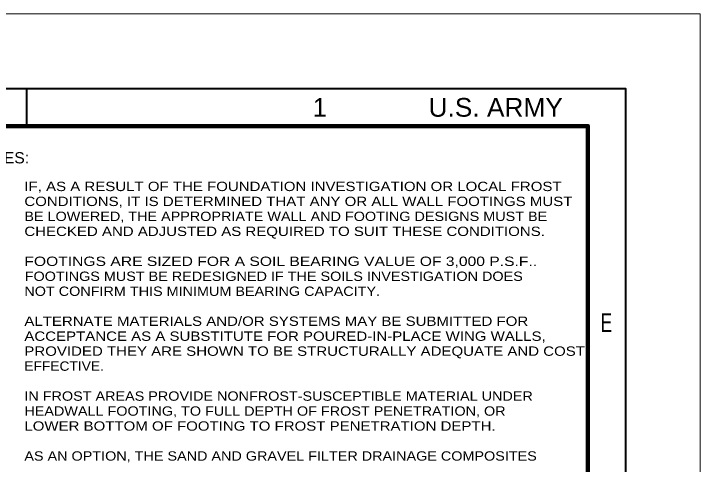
# Model space of a CAD drawing. Extents: x -22.3 to 19.7, y -11.8 to 18.2.
# Drawn here: x 10.52 to 19.69, y 12.14 to 18.16 of the extents above; entities that cross this region are included whole.
import ezdxf
from ezdxf.enums import TextEntityAlignment as Align

# ---------------------------------------------------------------- set-up
doc = ezdxf.new("R2010")
doc.units = 0
doc.header["$LTSCALE"] = 0.05
doc.layers.add('1', color=7, linetype='Continuous', lineweight=13)

msp = doc.modelspace()

# ---------------------------------------------------------------- linework, layer by layer
at = {"layer": '1', "lineweight": 40}
msp.add_line((10.69058, 17.16031), (10.69058, 16.66031), dxfattribs=at)
at = {"layer": '1'}
msp.add_lwpolyline([(-22.30942, 18.16031), (19.69058, 18.16031), (19.69058, -11.83969)], dxfattribs=at)
at = {"layer": '1', "lineweight": 40}
msp.add_lwpolyline([(-21.30942, -10.83969), (-21.30942, 17.16031), (18.69058, 17.16031), (18.69058, -10.83969)], close=True, dxfattribs=at)
at = {"layer": '1', "lineweight": 90}
msp.add_lwpolyline([(-19.80942, 16.66031), (18.19058, 16.66031), (18.19058, -10.33969), (-19.80942, -10.33969)], close=True, dxfattribs=at)

# ---------------------------------------------------------------- texts
at = {"layer": '1'}
msp.add_text('1', height=0.25, dxfattribs=at).set_placement((14.60758, 16.78531), align=Align.CENTER)
at = {"layer": '1', "width": 1.05}
msp.add_text('U.S. ARMY', height=0.25, dxfattribs=at).set_placement((17.85458, 16.78531), align=Align.RIGHT)
at = {"layer": '1'}
for s, height, width, p in [('NOTES:', 0.15, 1.05, (9.94025, 16.16198)), ('IF, AS A RESULT OF THE FOUNDATION INVESTIGATION OR LOCAL FROST', 0.125, 1.2, (10.66025, 15.79198)), ('CONDITIONS, IT IS DETERMINED THAT ANY OR ALL WALL FOOTINGS MUST', 0.125, 1.2, (10.66025, 15.59198)), ('BE LOWERED, THE APPROPRIATE WALL AND FOOTING DESIGNS MUST BE', 0.125, 1.15, (10.66025, 15.39198)), ('CHECKED AND ADJUSTED AS REQUIRED TO SUIT THESE CONDITIONS.', 0.125, 1.2, (10.66025, 15.19198)), ('FOOTINGS ARE SIZED FOR A SOIL BEARING VALUE OF 3,000 P.S.F..', 0.125, 1.25, (10.66025, 14.79198)), ('FOOTINGS MUST BE REDESIGNED IF THE SOILS INVESTIGATION DOES', 0.125, 1.15, (10.66525, 14.59198)), ('NOT CONFIRM THIS MINIMUM BEARING CAPACITY.', 0.125, 1.15, (10.66025, 14.39198)), ('ALTERNATE MATERIALS AND/OR SYSTEMS MAY BE SUBMITTED FOR', 0.125, 1.2, (10.66025, 13.99198)), ('ACCEPTANCE AS A SUBSTITUTE FOR POURED-IN-PLACE WING WALLS,', 0.125, 1.2, (10.66025, 13.79198)), ('PROVIDED THEY ARE SHOWN TO BE STRUCTURALLY ADEQUATE AND COST', 0.125, 1.2, (10.66025, 13.59198)), ('EFFECTIVE.', 0.125, 1.1, (10.66025, 13.39198)), ('IN FROST AREAS PROVIDE NONFROST-SUSCEPTIBLE MATERIAL UNDER', 0.125, 1.15, (10.66025, 12.99198)), ('HEADWALL FOOTING, TO FULL DEPTH OF FROST PENETRATION, OR', 0.125, 1.15, (10.66025, 12.79198)), ('LOWER BOTTOM OF FOOTING TO FROST PENETRATION DEPTH.', 0.125, 1.2, (10.66025, 12.59198)), ('AS AN OPTION, THE SAND AND GRAVEL FILTER DRAINAGE COMPOSITES', 0.125, 1.15, (10.66025, 12.19198))]:
    msp.add_text(s, height=height, dxfattribs=dict(at, width=width)).set_placement(p)
at = {"layer": '1', "width": 0.7}
msp.add_text('E', height=0.25, dxfattribs=at).set_placement((18.43558, 13.91031), align=Align.CENTER)

doc.saveas('drawing.dxf')
